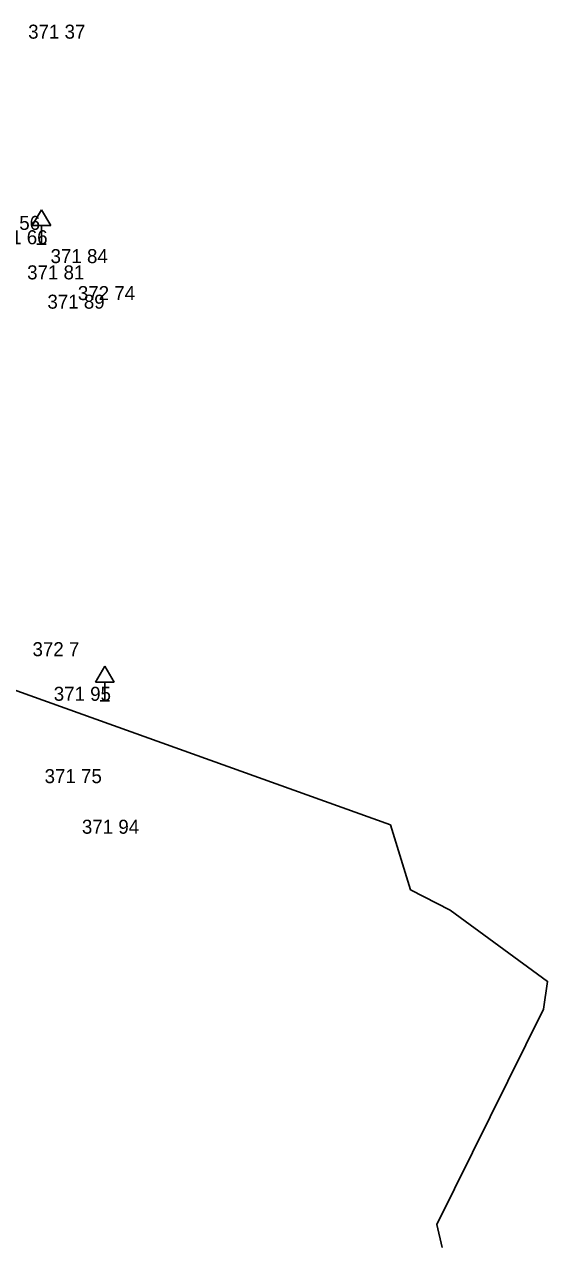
# Model space of a CAD drawing. Extents: x -688316 to -688024, y -973785 to -973591.
# Drawn here: x -688052.3 to -688024.2, y -973784.9 to -973719.4 of the extents above; entities that cross this region are included whole.
import ezdxf

# ---------------------------------------------------------------- set-up
doc = ezdxf.new("R2010")
doc.units = 0
doc.layers.add('Vrstva 3', color=7, linetype='Continuous')
doc.layers.add('Vrstva 34', color=7, linetype='Continuous')

# ---------------------------------------------------------------- blocks, each defined once
blk = doc.blocks.new('DZ')
at = {"layer": 'Vrstva 34'}
for p, q in [((-5, 10), (0, 18.5)), ((0, 18.5), (5, 10)), ((-5, 10), (5, 10)), ((0, 0), (0, 10)), ((-2.49, 0), (2.49, 0))]:
    blk.add_line(p, q, dxfattribs=at)

msp = doc.modelspace()

# ---------------------------------------------------------------- linework, layer by layer
at = {"layer": 'Vrstva 3'}
for points in [[(-688032.63, -973762.27), (-688053.63, -973754.76), (-688056.65, -973753.67), (-688062.72, -973747.24), (-688066.47, -973743), (-688066.073, -973742.092)], [(-688032.63, -973762.27), (-688053.63, -973754.76), (-688056.65, -973753.67), (-688062.72, -973747.24), (-688066.47, -973743), (-688066.073, -973742.092)], [(-688032.63, -973762.27), (-688053.63, -973754.76), (-688056.65, -973753.67), (-688062.72, -973747.24), (-688066.47, -973743), (-688066.073, -973742.092)], [(-688032.63, -973762.27), (-688053.63, -973754.76), (-688056.65, -973753.67), (-688062.72, -973747.24), (-688066.47, -973743), (-688066.073, -973742.092)], [(-688029.86, -973784.91), (-688030.14, -973783.68), (-688024.42, -973772.14), (-688024.21, -973770.66), (-688029.43, -973766.85), (-688031.55, -973765.75), (-688032.63, -973762.27)], [(-688029.86, -973784.91), (-688030.14, -973783.68), (-688024.42, -973772.14), (-688024.21, -973770.66), (-688029.43, -973766.85), (-688031.55, -973765.75), (-688032.63, -973762.27)], [(-688029.86, -973784.91), (-688030.14, -973783.68), (-688024.42, -973772.14), (-688024.21, -973770.66), (-688029.43, -973766.85), (-688031.55, -973765.75), (-688032.63, -973762.27)], [(-688029.86, -973784.91), (-688030.14, -973783.68), (-688024.42, -973772.14), (-688024.21, -973770.66), (-688029.43, -973766.85), (-688031.55, -973765.75), (-688032.63, -973762.27)]]:
    msp.add_lwpolyline(points, dxfattribs=at)

# ---------------------------------------------------------------- block references
at = {"layer": 'Vrstva 34', "xscale": 0.1, "yscale": 0.10000000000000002}
for p in [(-688051.33, -973731.18), (-688051.33, -973731.18), (-688047.94, -973755.63), (-688047.94, -973755.63)]:
    msp.add_blockref('DZ', p, dxfattribs=at)

# ---------------------------------------------------------------- texts
at = {"layer": 'Vrstva 3'}
for s, p in [('371 37 ', (-688052.051, -973720.17)), ('371 37 ', (-688052.051, -973720.17)), ('371 37 ', (-688052.051, -973720.17)), ('371 37 ', (-688052.051, -973720.17)), ('371 37 ', (-688052.051, -973720.17)), ('371 37 ', (-688052.051, -973720.17)), ('371 37 ', (-688052.051, -973720.17)), ('371 56 ', (-688054.479, -973730.41)), ('371 56 ', (-688054.479, -973730.41)), ('371 56 ', (-688054.479, -973730.41)), ('371 56 ', (-688054.479, -973730.41)), ('371 56 ', (-688054.479, -973730.41)), ('371 56 ', (-688054.479, -973730.41)), ('371 56 ', (-688054.479, -973730.41)), ('371 66 ', (-688054.078, -973731.18)), ('371 66 ', (-688054.078, -973731.18)), ('371 66 ', (-688054.078, -973731.18)), ('371 66 ', (-688054.078, -973731.18)), ('371 66 ', (-688054.078, -973731.18)), ('371 66 ', (-688054.078, -973731.18)), ('371 66 ', (-688054.078, -973731.18)), ('371 84 ', (-688050.849, -973732.19)), ('371 84 ', (-688050.849, -973732.19)), ('371 84 ', (-688050.849, -973732.19)), ('371 84 ', (-688050.849, -973732.19)), ('371 84 ', (-688050.849, -973732.19)), ('371 84 ', (-688050.849, -973732.19)), ('371 84 ', (-688050.849, -973732.19)), ('371 81 ', (-688052.105, -973733.06)), ('371 81 ', (-688052.105, -973733.06)), ('371 81 ', (-688052.105, -973733.06)), ('371 81 ', (-688052.105, -973733.06)), ('371 81 ', (-688052.105, -973733.06)), ('371 81 ', (-688052.105, -973733.06)), ('371 81 ', (-688052.105, -973733.06)), ('371 89 ', (-688051.019, -973734.63)), ('371 89 ', (-688051.019, -973734.63)), ('371 89 ', (-688051.019, -973734.63)), ('371 89 ', (-688051.019, -973734.63)), ('371 89 ', (-688051.019, -973734.63)), ('371 89 ', (-688051.019, -973734.63)), ('371 89 ', (-688051.019, -973734.63)), ('372 74 ', (-688049.387, -973734.17)), ('372 74 ', (-688049.387, -973734.17)), ('372 74 ', (-688049.387, -973734.17)), ('372 74 ', (-688049.387, -973734.17)), ('372 74 ', (-688049.387, -973734.17)), ('372 74 ', (-688049.387, -973734.17)), ('372 74 ', (-688049.387, -973734.17)), ('372 7  ', (-688051.818, -973753.24)), ('372 7  ', (-688051.818, -973753.24)), ('372 7  ', (-688051.818, -973753.24)), ('372 7  ', (-688051.818, -973753.24)), ('372 7  ', (-688051.818, -973753.24)), ('372 7  ', (-688051.818, -973753.24)), ('372 7  ', (-688051.818, -973753.24)), ('371 95 ', (-688050.679, -973755.63)), ('371 95 ', (-688050.679, -973755.63)), ('371 95 ', (-688050.679, -973755.63)), ('371 95 ', (-688050.679, -973755.63)), ('371 95 ', (-688050.679, -973755.63)), ('371 95 ', (-688050.679, -973755.63)), ('371 95 ', (-688050.679, -973755.63)), ('371 75 ', (-688051.169, -973760.04)), ('371 75 ', (-688051.169, -973760.04)), ('371 75 ', (-688051.169, -973760.04)), ('371 75 ', (-688051.169, -973760.04)), ('371 75 ', (-688051.169, -973760.04)), ('371 75 ', (-688051.169, -973760.04)), ('371 75 ', (-688051.169, -973760.04)), ('371 94 ', (-688049.169, -973762.75)), ('371 94 ', (-688049.169, -973762.75)), ('371 94 ', (-688049.169, -973762.75)), ('371 94 ', (-688049.169, -973762.75)), ('371 94 ', (-688049.169, -973762.75)), ('371 94 ', (-688049.169, -973762.75)), ('371 94 ', (-688049.169, -973762.75))]:
    msp.add_text(s, height=0.75, dxfattribs=at).set_placement(p)

doc.saveas('drawing.dxf')
